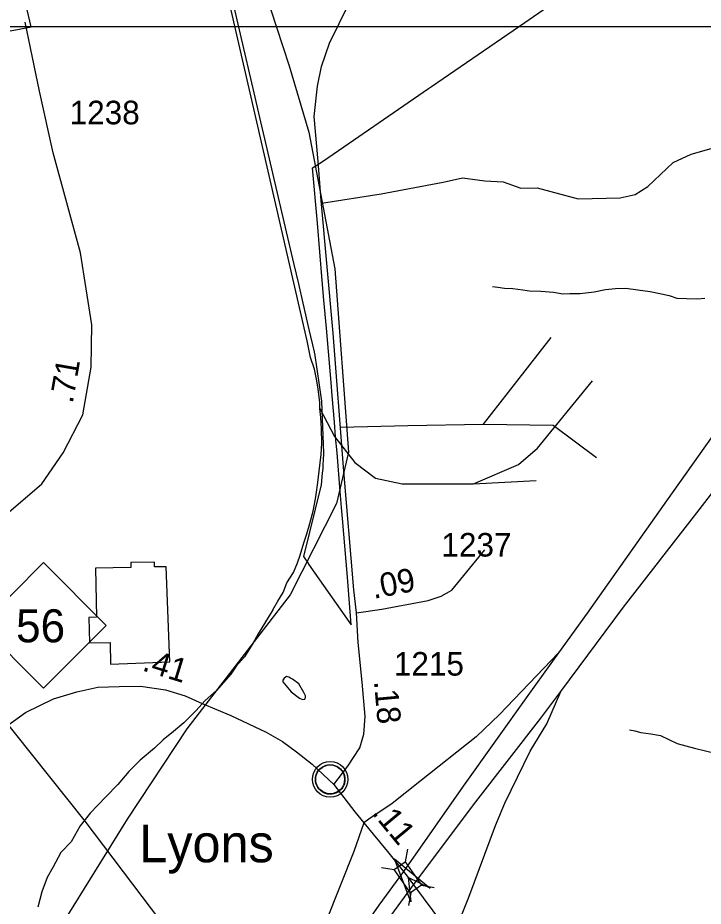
# Model space of a CAD drawing. Extents: x 2056842 to 2160602, y 826753 to 1016856.
# Drawn here: x 2079148 to 2082784, y 872595 to 877308 of the extents above; entities that cross this region are included whole.
import ezdxf

# ---------------------------------------------------------------- set-up
doc = ezdxf.new("R2010")
doc.units = 0
for name, color, linetype in [('Exist Boundary Land Use Reservation Military US Department of Defense', 7, 'Continuous'), ('Exist Boundary Political City Limit New', 7, 'Continuous'), ('Exist Civil Demographics Community CELL', 7, 'Continuous'), ('Exist Civil Demographics Community Label', 7, 'Continuous'), ('Exist Cultural Warehouse Building Footprint', 7, 'Continuous'), ('Exist Hydrographic Creek Single Shore', 7, 'Continuous'), ('Exist Hydrographic Misc Water Feature', 7, 'Continuous'), ('Exist Railroad Mainline', 7, 'Continuous'), ('Exist Railroad Siding', 7, 'Continuous'), ('Exist Road Non-System Type 51', 7, 'Continuous'), ('Exist Road Primary Interstate Divided Center Attributed', 7, 'Continuous'), ('Exist Road Primary Interstate Ramp 1 Lane Attributed', 7, 'Continuous'), ('Exist Road Primary NC Attributed', 7, 'Continuous'), ('Exist Road Primary NC Service Mileage Hundredths English Label', 7, 'Continuous'), ('Exist Road Primary NC Shield CELL', 7, 'Continuous'), ('Exist Road Primary NC Shield Number Label', 7, 'Continuous'), ('Exist Road Primary NC Structure Standard Bridge CELL', 7, 'Continuous'), ('Exist Road Secondary Mileage Hundredths English Label', 7, 'Continuous'), ('Exist Road Secondary Structure Standard Bridge Attributed CELL', 7, 'Continuous'), ('Exist Road Secondary Type 51 Attributed', 7, 'Continuous'), ('Exist Road Secondary Type 51 Number Label', 7, 'Continuous'), ('Exist Utilities Electrical Transmission Line', 7, 'Continuous'), ('Map Preparation Boundary City Limit Buffer Line', 7, 'Continuous'), ('Map Preparation Inset Cut Line', 7, 'Continuous')]:
    doc.layers.add(name, color=color, linetype=linetype)

msp = doc.modelspace()

# ---------------------------------------------------------------- linework, layer by layer
at = {"layer": 'Exist Boundary Land Use Reservation Military US Department of Defense'}
msp.add_lwpolyline([(2080977.6, 881572.9), (2080555.9, 880073.1), (2080317.1, 879347.8), (2080302.5, 879101.2), (2080290.8, 878801.8), (2080291.5, 878389), (2080333.3, 877928), (2080492.7, 877345.7), (2080521.2, 877257.6), (2080587.4, 877053.5), (2080691.7, 876700.5), (2080830.9, 875977.1), (2080902.2, 875003.6), (2080839.5, 874732.1), (2080592.5, 874246), (2080045.2, 873536.1), (2079729.3, 873057.2), (2079217.9, 872231.6)], dxfattribs=at)
at = {"layer": 'Exist Boundary Political City Limit New'}
for points in [[(2080008.9, 878592.9), (2080328, 877221.9), (2080400.5, 876910.3), (2080436.2, 876756.6), (2080457.5, 876665.2), (2080572.1, 876173.1), (2080612.5, 875999.8), (2080636.5, 875896.3), (2080660.5, 875793.3), (2080692.6, 875655.1), (2080720.5, 875535.2), (2080721.1, 875532.6), (2080722.4, 875529.6), (2080759, 875273.9), (2080759.1, 875272.1), (2080769.8, 875000), (2080768.4, 874960.2), (2080767.2, 874942.5), (2080765.8, 874917.8), (2080763.5, 874892.2), (2080758, 874830.9), (2080663.8, 874449.6), (2080690.2, 874411.4), (2080691.2, 874409.9), (2080917.5, 874086.8), (2080896.4, 874340.8), (2080870.5, 874651.6), (2080865.6, 874710.2), (2080858.6, 874795.4), (2080841.6, 875000), (2080834.4, 875085.1), (2080827.8, 875162.1), (2080815.8, 875301.8), (2080809.8, 875372.7), (2080785.1, 875661.1), (2080772.4, 875810.8), (2080763.4, 875915.1), (2080737.5, 876217.9), (2080712.4, 876512.6), (2080769.5, 876549.4), (2081327.6, 876932.8), (2081342.9, 876943.3), (2081837.5, 877283.1), (2082056.1, 877435.8)], [(2076664.9, 876790.1), (2079155.6, 877247.1), (2079219, 877260.4), (2078922.6, 878517.8)]]:
    msp.add_lwpolyline(points, dxfattribs=at)
at = {"layer": 'Exist Civil Demographics Community CELL'}
msp.add_lwpolyline([(2080727.9, 873280.1), (2080728.9, 873285.7), (2080730.7, 873292.2), (2080733.6, 873299.4), (2080736.5, 873305.2), (2080739.8, 873310.9), (2080743.6, 873316), (2080747.6, 873320.4), (2080752.2, 873325), (2080757.7, 873329.6), (2080763.1, 873333.3), (2080768, 873336.1), (2080773.1, 873338.6), (2080778.5, 873340.9), (2080784.1, 873342.7), (2080788.5, 873343.8), (2080793.3, 873344.6), (2080797.4, 873345.3), (2080803.8, 873345.6), (2080808.2, 873345.5), (2080813.9, 873345.2), (2080818.8, 873344.5), (2080823.7, 873343.5), (2080828.7, 873342.1), (2080833.9, 873340.1), (2080840.5, 873337.2), (2080846.8, 873333.7), (2080851.9, 873330.2), (2080857, 873326.2), (2080860.3, 873323), (2080864.5, 873318.6), (2080868.3, 873313.9), (2080871.4, 873309.4), (2080874.5, 873304.3), (2080877, 873299.2), (2080879, 873294.2), (2080880.6, 873289.2), (2080881.9, 873284.6), (2080883, 873278.5), (2080883.6, 873273.8), (2080883.9, 873267.8), (2080883.7, 873262), (2080883.1, 873256.3), (2080882.2, 873250.9), (2080880.5, 873244.7), (2080878.6, 873238.9), (2080876.3, 873233.8), (2080873.2, 873227.8), (2080869.9, 873222.5), (2080866.5, 873217.8), (2080862.2, 873213), (2080856.9, 873208.1), (2080851.9, 873204), (2080846.9, 873200.5), (2080842.6, 873198), (2080835.8, 873194.8), (2080828.6, 873192.1), (2080822.7, 873190.6), (2080816.1, 873189.3), (2080811.6, 873188.8), (2080807.1, 873188.6), (2080801.6, 873188.6), (2080797.3, 873189), (2080791.7, 873189.7), (2080785.7, 873191), (2080781.1, 873192.3), (2080776, 873194.2), (2080771.4, 873196.2), (2080767.5, 873198.4), (2080760.7, 873202.5), (2080755.1, 873206.8), (2080750.2, 873211.3), (2080745.7, 873216.1), (2080742.5, 873220.1), (2080739.6, 873224.3), (2080735.5, 873231.4), (2080733.7, 873234.9), (2080732, 873238.9), (2080729.4, 873247.1), (2080727.9, 873254.2), (2080727.2, 873259.3), (2080726.9, 873265.6), (2080726.8, 873270.3), (2080727.4, 873276.8)], close=True, dxfattribs=at)
for centre, radius in [((2080805.5, 873267.7), 94.3), ((2080805.2, 873267.9), 76.7)]:
    msp.add_circle(centre, radius, dxfattribs=at)
at = {"layer": 'Exist Cultural Warehouse Building Footprint'}
msp.add_lwpolyline([(2079955.3, 873890.9), (2079935.8, 874394.9), (2079873.4, 874395.9), (2079873.4, 874420.3), (2079747.7, 874417.9), (2079747.3, 874391.7), (2079560.9, 874387.3), (2079565.3, 874128.3), (2079524.3, 874126), (2079529.5, 873991.7), (2079637.8, 873994), (2079640.3, 873878)], close=True, dxfattribs=at)
at = {"layer": 'Exist Hydrographic Creek Single Shore'}
for points in [[(2081666.4, 875883.3), (2081694.3, 875879.5), (2081730.2, 875873.5), (2081774.1, 875871.8), (2081828, 875864), (2081862.2, 875860), (2081922.3, 875858.2), (2081990.6, 875852.3), (2082040.2, 875844.4), (2082076.3, 875844.6), (2082132.1, 875844.7), (2082206.5, 875855), (2082266.2, 875867.4), (2082318.3, 875871.3), (2082374.4, 875873.7), (2082438, 875865.6), (2082502.4, 875855.9), (2082562.5, 875844.4), (2082604.1, 875834.3), (2082644.3, 875820.6), (2082696.2, 875818.4), (2082752.6, 875816.7), (2082792.3, 875820.9)], [(2082393.7, 873529.9), (2082421.6, 873526), (2082453.4, 873515.9), (2082505.5, 873510), (2082557.6, 873500.5), (2082645.7, 873458.7), (2082738, 873433), (2082854.1, 873405.3)]]:
    msp.add_lwpolyline(points, dxfattribs=at)
at = {"layer": 'Exist Hydrographic Misc Water Feature'}
msp.add_lwpolyline([(2080672.9, 873698.3), (2080674.7, 873702.5), (2080674.5, 873710.6), (2080666.3, 873728.5), (2080638.4, 873774.6), (2080606, 873800.1), (2080594.4, 873804.3), (2080586.6, 873810.3), (2080574.5, 873814.2), (2080560.5, 873804.2), (2080554.6, 873794.1), (2080554.4, 873786), (2080562.2, 873774.2), (2080598.7, 873732.3), (2080642.8, 873698.4), (2080658.7, 873690.7), (2080670.6, 873692.5), (2080672.9, 873698.3)], dxfattribs=at)
at = {"layer": 'Exist Railroad Mainline'}
for points in [[(2080500.5, 874166.6), (2080528.4, 874212.6), (2080556.2, 874258.6), (2080576.1, 874310.6), (2080610, 874364.7), (2080631.9, 874416.9), (2080645.7, 874457), (2080665.5, 874523), (2080681.3, 874571.1), (2080697.2, 874625.2), (2080714.9, 874691.2), (2080726.7, 874755.2), (2080730.6, 874779.1), (2080740.5, 874843.1), (2080746.3, 874903.2), (2080758, 874991.1), (2080761.8, 875051.3), (2080759.6, 875127.1), (2080755.4, 875187.2), (2080751.2, 875235.1), (2080751.1, 875267.1), (2080741, 875339.1), (2080732.6, 875391.1), (2080722.5, 875443.1), (2080700.4, 875505), (2080684, 875594.9), (2080073.9, 878250.8)], [(2080500.5, 874166.6), (2080456.8, 874094.3), (2080423.1, 874040.2), (2080395.2, 873988.1), (2080351.3, 873918), (2080307.5, 873867.9), (2080277.6, 873825.7), (2080239.9, 873781.7), (2080202, 873739.5), (2080142.1, 873685.3), (2080092.4, 873631.3), (2080028.5, 873567.1), (2079974.7, 873521), (2079918.8, 873476.7), (2079872.9, 873432.7), (2079797.2, 873370.4), (2079737.3, 873310.2), (2079679.7, 873240), (2079615.7, 873175.7), (2079572, 873131.6), (2079532.1, 873087.5), (2079478.3, 873021.4), (2079430.6, 872937.1), (2079376.8, 872879.1), (2079335, 872800.9), (2079303.3, 872747), (2079275.5, 872670.7), (2079253.8, 872588.8)]]:
    msp.add_lwpolyline(points, dxfattribs=at)
at = {"layer": 'Exist Railroad Siding'}
msp.add_line((2081565.7, 874835.8), (2081898.2, 874854), dxfattribs=at)
for points in [[(2081565.7, 874835.8), (2081803.7, 874937.7), (2081905.5, 875024.9), (2082196.2, 875381.3)], [(2080751.2, 875235.1), (2080827.9, 875086.8), (2080936.9, 874948.6), (2081046, 874864.9), (2081187.7, 874835.8), (2081565.7, 874835.8)]]:
    msp.add_lwpolyline(points, dxfattribs=at)
at = {"layer": 'Exist Road Non-System Type 51'}
for points in [[(2080758.8, 876324.3), (2081076.4, 876374.4), (2081404.1, 876435.5), (2081507.6, 876458.6), (2081625.3, 876443.7), (2081723.6, 876437.8), (2081817.5, 876403.5), (2081903.9, 876406.5), (2082121.3, 876346.8), (2082344, 876353.5), (2082423, 876371.4), (2082490, 876413.2), (2082625.6, 876539.9), (2082720.2, 876585.3), (2083056.8, 876680.7), (2083207.3, 876741.8), (2083369.6, 876773.1), (2083447.8, 876766.4)], [(2081619.3, 875152.8), (2081795.9, 875378.7), (2081976.8, 875612)], [(2080859.9, 875136.1), (2081217.1, 875145.4), (2081619.3, 875152.8)], [(2081619.3, 875152.8), (2081988, 875147.6), (2082218.9, 874974.7)], [(2081394.5, 874239.8), (2081450.6, 874271.5), (2081624.9, 874484.7)]]:
    msp.add_lwpolyline(points, dxfattribs=at)
at = {"layer": 'Exist Road Primary Interstate Divided Center Attributed'}
for points in [[(2086913.8, 881656.6), (2086812.4, 881495.1), (2086697.2, 881298.8), (2086416.5, 880823.6), (2086104.3, 880294.3), (2085757.9, 879705.6), (2085389, 879075.5), (2085071.4, 878540.8), (2084756.5, 877997.1), (2084428.1, 877431.8), (2084115.8, 876911.6), (2083719, 876326.5), (2083315.1, 875763), (2082934.5, 875231.9), (2082589.9, 874745.8), (2082168.8, 874149.9), (2082016.5, 873938.4)], [(2082028.6, 873734.2), (2082362.2, 874180.5), (2082750, 874681), (2083148.6, 875195.9), (2083527.4, 875694.6), (2083900.8, 876187.9), (2084261.6, 876715.3), (2084561.2, 877205), (2084920.2, 877849.5), (2085220.7, 878395), (2085715.6, 879311.3), (2085981, 879788.4), (2086215.9, 880224.1), (2086495.7, 880739), (2086767.4, 881239.4), (2086966.9, 881577.7)], [(2082016.5, 873938.4), (2081853.9, 873712.5), (2081511, 873231.8), (2081193.6, 872778.4)], [(2081247.1, 872708.7), (2081577.6, 873149), (2081922.2, 873591.9), (2082028.6, 873734.2)], [(2081193.6, 872778.4), (2081063.9, 872599.9), (2080749.9, 872151.6), (2080408.9, 871640.4)], [(2080401.7, 871499.9), (2080812.8, 872094), (2081132.3, 872551.3), (2081247.1, 872708.7)]]:
    msp.add_lwpolyline(points, dxfattribs=at)
at = {"layer": 'Exist Road Primary Interstate Ramp 1 Lane Attributed'}
for points in [[(2082016.5, 873938.4), (2081703.3, 873611.5), (2081579.7, 873494.1), (2081280.1, 873255.6), (2081134.7, 873139.2), (2081010.1, 873057.1), (2080983.6, 873037.9)], [(2081446.9, 872439.8), (2081468.1, 872461.6), (2081540.8, 872642.5), (2081681.5, 873023.3), (2081731.3, 873141.8), (2081865.8, 873416.7), (2081955.1, 873562.1), (2082028.6, 873734.2)], [(2080983.6, 873037.9), (2080930.7, 872885.1), (2080781.7, 872512.6), (2080632.6, 872127.5), (2080470.1, 871794.5), (2080408.9, 871640.4)]]:
    msp.add_lwpolyline(points, dxfattribs=at)
at = {"layer": 'Exist Road Primary NC Attributed'}
for points in [[(2078891.9, 873393), (2079093.8, 873553.2), (2079188.4, 873623.3), (2079336.9, 873694.5), (2079460.6, 873731.7), (2079572.3, 873756.3), (2079685.5, 873760.8), (2079799.8, 873762.7), (2079931.7, 873742.5), (2080035.9, 873710.5), (2080127, 873670.8), (2080277.7, 873607.2), (2080465.1, 873517.9), (2080551.8, 873468.9), (2080627.2, 873413.6), (2080710.2, 873348.2), (2080825.4, 873241)], [(2080825.4, 873241), (2080936.4, 873094.9), (2080983.6, 873037.9)], [(2080983.6, 873037.9), (2081117, 872876.9), (2081193.6, 872778.4)], [(2081193.6, 872778.4), (2081218.3, 872746.5), (2081247.1, 872708.7)], [(2081247.1, 872708.7), (2081446.9, 872439.8)]]:
    msp.add_lwpolyline(points, dxfattribs=at)
at = {"layer": 'Exist Road Primary NC Shield CELL'}
msp.add_lwpolyline([(2078951.9, 874084.6), (2079284.9, 874417.6), (2079617.9, 874084.6), (2079284.9, 873751.6)], close=True, dxfattribs=at)
at = {"layer": 'Exist Road Primary NC Structure Standard Bridge CELL'}
for p, q in [((2081214.7, 872897.5), (2081202.7, 872829.5)), ((2081076.9, 872801), (2081144.9, 872789)), ((2081232.6, 872666), (2081220.6, 872598)), ((2081289.1, 872705.6), (2081357.1, 872693.6))]:
    msp.add_line(p, q, dxfattribs=at)
msp.add_lwpolyline([(2081202.7, 872829.5), (2081289.4, 872705.8), (2081231.6, 872665.3), (2081144.9, 872789)], close=True, dxfattribs=at)
at = {"layer": 'Exist Road Secondary Structure Standard Bridge Attributed CELL'}
msp.add_lwpolyline([(2081233.5, 872617.5), (2081147.1, 872845.4), (2081335.9, 872691.2), (2081218.3, 872746.5)], close=True, dxfattribs=at)
at = {"layer": 'Exist Road Secondary Type 51 Attributed'}
for points in [[(2080944.4, 874151.9), (2080931, 874272.6), (2080876.6, 874923.3), (2080820.8, 875635), (2080757.5, 876339.4), (2080741.1, 876545.1), (2080720.2, 876785), (2080737.4, 876945.3), (2080759.7, 877049.6), (2080801.4, 877173.3), (2081056.9, 877692.8), (2081437.5, 878425.4), (2081745.1, 879025.4), (2081797.2, 879186.4), (2081832.9, 879328), (2081833.7, 879540.4), (2081829.2, 879671.6), (2081725.7, 880161.3), (2081710.8, 880356.5), (2081722.8, 880492.1), (2081731.9, 880570.6), (2081769.3, 880697.6), (2081814.1, 880828.1), (2081886.2, 881033.6)], [(2078362.4, 874052.6), (2079275.7, 874835.7), (2079388.2, 875000.4), (2079492.7, 875201.3), (2079536.9, 875454.4), (2079540.9, 875679.4), (2079480.6, 876061.1), (2079336, 876591.4), (2079263.7, 876918.9), (2079187.3, 877284.5)], [(2080944.4, 874151.9), (2081080, 874169.8), (2081325.7, 874217.5), (2081394.5, 874239.8)], [(2080825.4, 873241), (2080899, 873338), (2080963.4, 873434.6), (2080983.5, 873507.6), (2080991.3, 873601.1), (2080974.9, 873783), (2080954.1, 873993.2), (2080944.4, 874151.9)]]:
    msp.add_lwpolyline(points, dxfattribs=at)
at = {"layer": 'Exist Utilities Electrical Transmission Line'}
msp.add_lwpolyline([(2079289.6, 845905.8), (2079948.4, 849305.4), (2079483.2, 855866.2), (2080101, 858353.8), (2081583.8, 864201.8), (2082616, 868304.1), (2080660.7, 871519), (2079505, 873046.5), (2077150, 875999.6), (2076168.7, 877076.1), (2079417.8, 882691.3), (2077477.1, 888146.6), (2075950.7, 892161.6), (2073748.3, 895216.6), (2070106.7, 900031.7)], dxfattribs=at)
at = {"layer": 'Map Preparation Boundary City Limit Buffer Line'}
for points in [[(2080008.9, 878592.9), (2080328, 877221.9), (2080400.5, 876910.3), (2080436.2, 876756.6), (2080457.5, 876665.2), (2080572.1, 876173.1), (2080612.5, 875999.8), (2080636.5, 875896.3), (2080660.5, 875793.3), (2080692.6, 875655.1), (2080720.5, 875535.2), (2080721.1, 875532.6), (2080722.4, 875529.6), (2080759, 875273.9), (2080759.1, 875272.1), (2080769.8, 875000), (2080768.4, 874960.2), (2080767.2, 874942.5), (2080765.8, 874917.8), (2080763.5, 874892.2), (2080758, 874830.9), (2080663.8, 874449.6), (2080690.2, 874411.4), (2080691.2, 874409.9), (2080917.5, 874086.8), (2080896.4, 874340.8), (2080870.5, 874651.6), (2080865.6, 874710.2), (2080858.6, 874795.4), (2080841.6, 875000), (2080834.4, 875085.1), (2080827.8, 875162.1), (2080815.8, 875301.8), (2080809.8, 875372.7), (2080785.1, 875661.1), (2080772.4, 875810.8), (2080763.4, 875915.1), (2080737.5, 876217.9), (2080712.4, 876512.6), (2080769.5, 876549.4), (2081327.6, 876932.8), (2081342.9, 876943.3), (2081837.5, 877283.1), (2082056.1, 877435.8)], [(2076664.9, 876790.1), (2079155.6, 877247.1), (2079219, 877260.4), (2078922.6, 878517.8)]]:
    msp.add_lwpolyline(points, dxfattribs=at)
at = {"layer": 'Map Preparation Inset Cut Line'}
msp.add_lwpolyline([(2059276.8, 845851.8), (2104036.2, 845851.8), (2104036.2, 868310.8), (2085975.1, 868308.6), (2085982, 877260.1), (2059276.8, 877260.1), (2059276.8, 845851.8)], dxfattribs=at)

# ---------------------------------------------------------------- texts
at = {"layer": 'Exist Civil Demographics Community Label'}
msp.add_text('Lyons', height=200, dxfattribs=at).set_placement((2079792.5, 872827.7))
at = {"layer": 'Exist Road Primary NC Service Mileage Hundredths English Label'}
for s, rotation, p in [('.41', 342.9151, (2079803.5, 873846.7)), ('.11', 309.6418, (2081022.5, 873088.8))]:
    msp.add_text(s, height=125, rotation=rotation, dxfattribs=at).set_placement(p)
at = {"layer": 'Exist Road Primary NC Shield Number Label'}
msp.add_text('56', height=175, dxfattribs=at).set_placement((2079139, 873994.9))
at = {"layer": 'Exist Road Secondary Mileage Hundredths English Label'}
for s, rotation, p in [('.71', 80.0962, (2079439.2, 875258.4)), ('.09', 10.9829, (2081036.3, 874225)), ('.18', 275.1485, (2081037.2, 873788.3))]:
    msp.add_text(s, height=125, rotation=rotation, dxfattribs=at).set_placement(p)
at = {"layer": 'Exist Road Secondary Type 51 Number Label'}
for s, p in [('1238', (2079423.3, 876743)), ('1237', (2081395.4, 874449.8)), ('1215', (2081143, 873818.1))]:
    msp.add_text(s, height=125, dxfattribs=at).set_placement(p)

doc.saveas('drawing.dxf')
